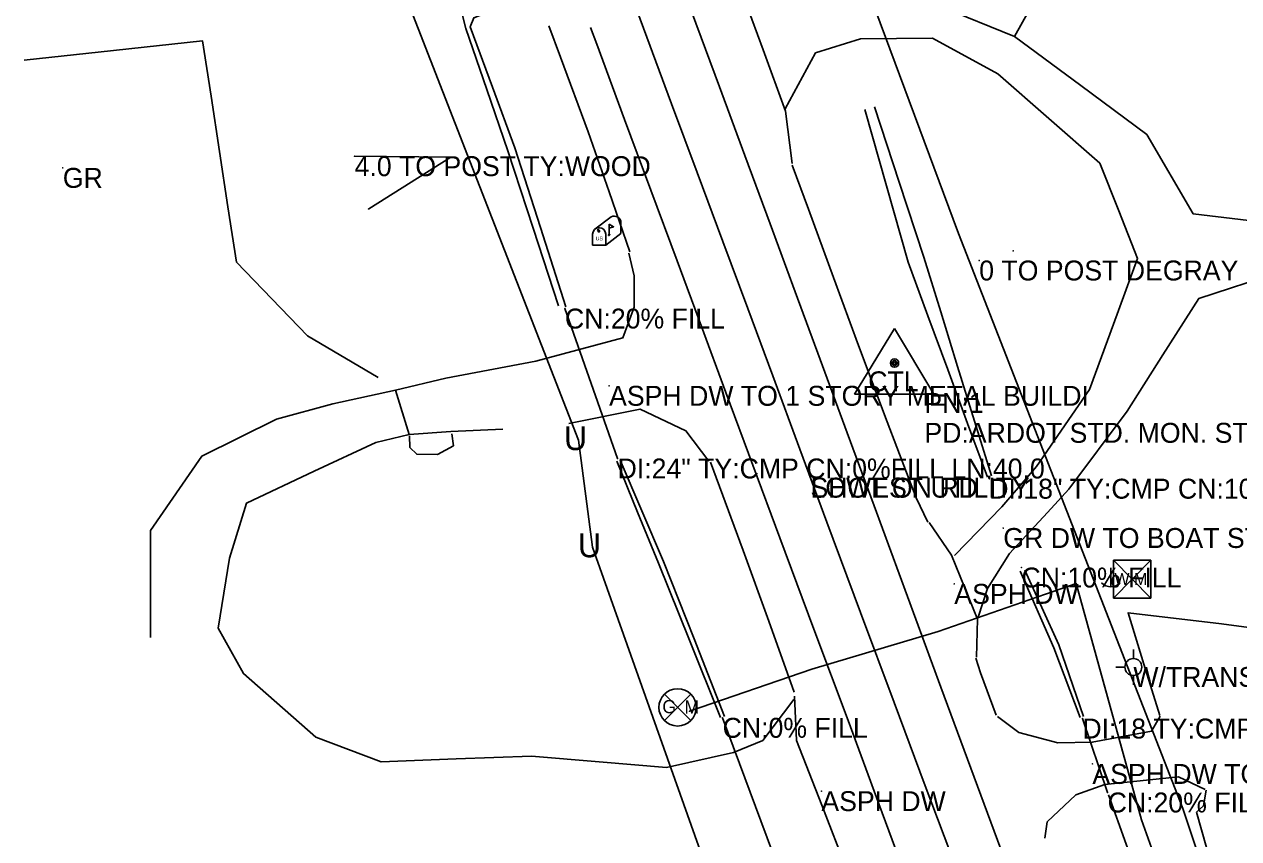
# Model space of a CAD drawing. Extents: x 954793 to 988390, y 1867850 to 1924428.
# Drawn here: x 987769.4 to 988074.1, y 1868561.6 to 1868765.9 of the extents above; entities that cross this region are included whole.
import ezdxf

# ---------------------------------------------------------------- set-up
doc = ezdxf.new("R2010")
doc.units = 0
for name, color, linetype in [('Default', 7, 'Continuous'), ('S_DITCHLINE', 7, 'Continuous'), ('S_DRG_PT_SYM', 7, 'Continuous'), ('S_DRIVEWAY', 7, 'Continuous'), ('S_EDGE_CONCRETE', 7, 'Continuous'), ('S_EDGE_PAVEMENT', 7, 'Continuous'), ('S_ELECTRIC_UTILITIES_ANNOT', 7, 'Continuous'), ('S_FIBER_OPTIC_CABLE', 7, 'Continuous'), ('S_GAS_UTILITIES', 7, 'Continuous'), ('S_GRD_PT_SYM', 7, 'Continuous'), ('S_MAILBOX', 7, 'Continuous'), ('S_MISC_TOPO_POINT', 7, 'Continuous'), ('S_MSC_PT_SYM', 7, 'Continuous'), ('S_PARKING', 7, 'Continuous'), ('S_PAVEMENT_CROWN', 7, 'Continuous'), ('S_PRIMARY_CTL', 7, 'Continuous'), ('S_PRIMARY_CTL_ANNOT', 7, 'Continuous'), ('S_SHOULDER', 7, 'Continuous'), ('S_SIDE_DRAIN', 7, 'Continuous'), ('S_SIDE_DRAIN_ANNOT', 7, 'Continuous'), ('S_SIGN', 7, 'Continuous'), ('S_SIGN_ANNOT', 7, 'Continuous'), ('S_SURVEY_TEXT_ANNOT', 7, 'Continuous'), ('S_TRAILS', 7, 'Continuous'), ('S_UNDERGROUND_CABLE', 7, 'Continuous'), ('S_UTILITY_POLE', 7, 'Continuous'), ('S_UTILITY_POLE_ANNOT', 7, 'Continuous'), ('S_UTL_PT_SYM', 7, 'Continuous'), ('S_WATER_UTILITIES', 7, 'Continuous')]:
    doc.layers.add(name, color=color, linetype=linetype)

msp = doc.modelspace()

# ---------------------------------------------------------------- linework, layer by layer
at = {"layer": 'S_DITCHLINE'}
for points in [[(987903.49, 1868695.28), (987897.13, 1868714.75), (987890.76, 1868734.22), (987885.5, 1868749.56), (987880.23, 1868764.91), (987878.83, 1868770.15), (987872.06, 1868784.34), (987865.3, 1868798.52), (987858.54, 1868812.7), (987851.78, 1868826.88), (987846.31, 1868841.55), (987840.85, 1868856.22), (987834.35, 1868875.57), (987827.85, 1868894.92), (987821.35, 1868914.27), (987814.85, 1868933.62), (987807.68, 1868952.16), (987800.51, 1868970.69), (987793.34, 1868989.23), (987786.17, 1869007.76)], [(987905.32, 1868695.02), (987898.91, 1868714.97), (987892.51, 1868734.92), (987886.89, 1868750.13), (987881.26, 1868765.33), (987882.21, 1868767.55), (987892.86, 1868771.75)], [(987980.33, 1868744.56), (987985.73, 1868725.41), (987991.13, 1868706.25), (987996.11, 1868692.76), (988001.09, 1868679.27), (988006.06, 1868665.78), (988011.04, 1868652.28)], [(987982.74, 1868745.21), (987988.9, 1868726.34), (987995.07, 1868707.48), (987999.32, 1868693.77), (988003.57, 1868680.07), (988007.81, 1868666.36), (988012.06, 1868652.65)], [(987944.08, 1868592.01), (987936.31, 1868611.36), (987928.54, 1868630.7), (987923.3, 1868643.5), (987918.06, 1868656.3)], [(987945.12, 1868592.24), (987937.47, 1868611.69), (987929.83, 1868631.15), (987924.35, 1868643.86), (987918.88, 1868656.56)], [(988034.35, 1868592.01), (988027.69, 1868609.51), (988019.26, 1868628.71)], [(988035.15, 1868592.21), (988028.96, 1868610.19), (988020.44, 1868628.99)], [(988041.44, 1868572.59), (988045.86, 1868560.2), (988050.29, 1868547.82), (988054.72, 1868535.44), (988059.14, 1868523.05)]]:
    msp.add_lwpolyline(points, dxfattribs=at)
at = {"layer": 'S_DRG_PT_SYM'}
for points in [[(987905.07, 1868694.59), (987905.07, 1868694.64), (987905.07, 1868694.59), (987905.02, 1868694.59), (987905.07, 1868694.59), (987905.07, 1868694.54), (987905.07, 1868694.59), (987905.12, 1868694.59)], [(987918.27, 1868656.97), (987918.27, 1868657.02), (987918.27, 1868656.97), (987918.22, 1868656.97), (987918.27, 1868656.97), (987918.27, 1868656.92), (987918.27, 1868656.97), (987918.32, 1868656.97)], [(988011.51, 1868651.9), (988011.51, 1868651.95), (988011.51, 1868651.9), (988011.46, 1868651.9), (988011.51, 1868651.9), (988011.51, 1868651.85), (988011.51, 1868651.9), (988011.56, 1868651.9)], [(988019.58, 1868629.61), (988019.58, 1868629.66), (988019.58, 1868629.61), (988019.53, 1868629.61), (988019.58, 1868629.61), (988019.58, 1868629.56), (988019.58, 1868629.61), (988019.63, 1868629.61)], [(987944.62, 1868591.9), (987944.62, 1868591.95), (987944.62, 1868591.9), (987944.57, 1868591.9), (987944.62, 1868591.9), (987944.62, 1868591.85), (987944.62, 1868591.9), (987944.67, 1868591.9)], [(988034.87, 1868591.72), (988034.87, 1868591.77), (988034.87, 1868591.72), (988034.82, 1868591.72), (988034.87, 1868591.72), (988034.87, 1868591.67), (988034.87, 1868591.72), (988034.92, 1868591.72)], [(988041.2, 1868573.16), (988041.2, 1868573.21), (988041.2, 1868573.16), (988041.15, 1868573.16), (988041.2, 1868573.16), (988041.2, 1868573.11), (988041.2, 1868573.16), (988041.25, 1868573.16)]]:
    msp.add_lwpolyline(points, dxfattribs=at)
at = {"layer": 'S_DRIVEWAY'}
msp.add_line((987857.66, 1868660.97), (987865.96, 1868663.02), dxfattribs=at)
for points in [[(987962.03, 1868730.96), (987960.37, 1868744.14), (987954.75, 1868759.55), (987949.14, 1868774.97), (987943.2, 1868781.9)], [(988084.35, 1868715.79), (988062.66, 1868718.35), (988051.03, 1868738.3), (988034.45, 1868750.58), (988017.86, 1868762.86), (987999.71, 1868770.22), (987977.93, 1868773.05), (987963.85, 1868772.04), (987949.58, 1868775.12)], [(988002.79, 1868632.68), (988014.67, 1868644.85), (988023.39, 1868654.95), (988036.69, 1868674.27), (988042.7, 1868690.71), (988048.71, 1868707.15), (988043.98, 1868719.11), (988039.26, 1868731.06), (988026.45, 1868742.29), (988013.64, 1868753.52), (987997.23, 1868762.45), (987979.17, 1868762.29), (987967.96, 1868758.76), (987960.32, 1868744.73)], [(987889.49, 1868664.37), (987889.47, 1868664.37), (987876.44, 1868663.74), (987865.96, 1868663.02), (987862.6, 1868674.15), (987875.18, 1868677.1), (987897.73, 1868681.36), (987919.55, 1868687.22), (987922.42, 1868694.94), (987922.47, 1868702.78), (987921.13, 1868708.51)], [(988008.75, 1868617.14), (988011.05, 1868624.4), (988016.57, 1868633.1), (988026.12, 1868643.41), (988031.44, 1868649.3), (988046.06, 1868668.83), (988055.06, 1868682.98), (988064.06, 1868697.13), (988084.06, 1868703.69)], [(987862.6, 1868674.15), (987846.84, 1868670.68), (987832.73, 1868666.82), (987813.97, 1868657.55), (987801.11, 1868638.92), (987801.1, 1868625.5), (987801.09, 1868612.08)], [(987941.2, 1868656.29), (987935.42, 1868663.91), (987923.93, 1868669.37), (987906, 1868665.72)], [(987962.48, 1868596.49), (987954.67, 1868586.23), (987947.39, 1868583.22), (987930.55, 1868579.48), (987913.61, 1868580.9), (987896.67, 1868582.32), (987877.82, 1868581.61), (987858.98, 1868580.89), (987842.61, 1868587.03), (987824.39, 1868603.03), (987818.08, 1868614.37), (987820.88, 1868631.96), (987825.2, 1868645.8), (987842.16, 1868653.83), (987857.66, 1868660.97)], [(988008.33, 1868607.12), (988008.53, 1868616.63), (988002.03, 1868632.69), (987996.47, 1868640.88)], [(988054.28, 1868592.51), (988050.3, 1868605.39), (988046.32, 1868618.26), (988069.77, 1868615.5), (988087.92, 1868613.07), (988106.06, 1868610.64), (988126.98, 1868607.84), (988129.98, 1868594.59), (988132.97, 1868581.34)], [(987982.53, 1868545.39), (987975.81, 1868553.73), (987969.49, 1868569.96), (987963.16, 1868586.18), (987962.64, 1868597.36)], [(988013.57, 1868592.27), (988018.93, 1868588.25), (988028.74, 1868585.64), (988037.33, 1868585.79), (988052.24, 1868588.54), (988054.39, 1868592.31)], [(988065.68, 1868573.91), (988058.99, 1868577.08), (988040.51, 1868575.17), (988033.25, 1868572.61), (988026.03, 1868565.78), (988025.41, 1868561.72)], [(988073.78, 1868531.66), (988068.65, 1868549.95), (988063.53, 1868568.24), (988065.28, 1868569.79), (988065.92, 1868573.75)]]:
    msp.add_lwpolyline(points, dxfattribs=at)
at = {"layer": 'S_EDGE_CONCRETE'}
msp.add_lwpolyline([(987876.7, 1868663.18), (987877.12, 1868660.17), (987873.13, 1868658), (987867.91, 1868658.03), (987866.18, 1868659.72), (987866.08, 1868662.65)], dxfattribs=at)
at = {"layer": 'S_EDGE_PAVEMENT'}
for points in [[(988087.92, 1868362.44), (988083.33, 1868374.33), (988078.74, 1868386.23), (988074.15, 1868398.13), (988069.56, 1868410.02), (988061.2, 1868432.59), (988052.85, 1868455.16), (988045.81, 1868474.26), (988038.77, 1868493.37), (988034.38, 1868505.17), (988029.98, 1868516.96), (988022.2, 1868537.95), (988014.42, 1868558.95), (988006.89, 1868579.28), (987999.36, 1868599.62), (987991.01, 1868622.37), (987982.66, 1868645.12), (987975.89, 1868663.45), (987969.13, 1868681.78), (987962.84, 1868698.82), (987956.56, 1868715.86), (987950.21, 1868733.04), (987943.85, 1868750.23), (987936.81, 1868769.13)], [(987991.56, 1868549.36), (987983.82, 1868570.3), (987976.09, 1868591.24), (987967.51, 1868614.15), (987958.93, 1868637.07), (987952.19, 1868655.33), (987945.45, 1868673.58), (987939.33, 1868690.06), (987933.21, 1868706.54), (987926.62, 1868724.29), (987920.03, 1868742.04), (987913.06, 1868760.92), (987911.5, 1868765.16)]]:
    msp.add_lwpolyline(points, dxfattribs=at)
at = {"layer": 'S_FIBER_OPTIC_CABLE'}
for p, q in [((988003.79, 1868713.46), (987979.41, 1868779.14)), ((988060.06, 1868569.17), (988003.79, 1868713.46)), ((988084.77, 1868494.79), (988060.06, 1868569.17))]:
    msp.add_line(p, q, dxfattribs=at)
at = {"layer": 'S_GAS_UTILITIES'}
for p, q in [((988033.28, 1868625.59), (987998.69, 1868613.56)), ((988049.72, 1868566.28), (988033.28, 1868625.59)), ((987998.69, 1868613.56), (987967.02, 1868604.12)), ((987967.02, 1868604.12), (987936.32, 1868593.56)), ((987930.01, 1868591.22), (987936.63, 1868597.84)), ((987930.01, 1868597.84), (987936.63, 1868591.22)), ((988074.37, 1868497.19), (988049.72, 1868566.28))]:
    msp.add_line(p, q, dxfattribs=at)
msp.add_circle((987933.32, 1868594.53), 4.68, dxfattribs=at)
at = {"layer": 'S_GRD_PT_SYM'}
msp.add_lwpolyline([(987966.66, 1868652.16), (987966.66, 1868652.21), (987966.66, 1868652.16), (987966.61, 1868652.16), (987966.66, 1868652.16), (987966.66, 1868652.11), (987966.66, 1868652.16), (987966.71, 1868652.16)], dxfattribs=at)
at = {"layer": 'S_MAILBOX'}
for p, q in [((987912.55, 1868714.5), (987916.69, 1868717.61)), ((987916.17, 1868715.79), (987916.17, 1868713.08)), ((987919.12, 1868716.14), (987919.12, 1868713.42)), ((987912, 1868713.23), (987912, 1868710.51)), ((987915.32, 1868710.51), (987919.12, 1868713.42)), ((987915.32, 1868713.23), (987915.32, 1868710.51)), ((987912, 1868710.51), (987915.32, 1868710.51))]:
    msp.add_line(p, q, dxfattribs=at)
for points in [[(987913.18, 1868714.34), (987913.4, 1868714.21), (987913.4, 1868713.82), (987913.71, 1868713.82), (987913.71, 1868714.18), (987913.52, 1868714.43), (987913.18, 1868714.37)], [(987916.17, 1868715.79), (987917.28, 1868715.13), (987916.17, 1868714.78)]]:
    msp.add_lwpolyline(points, dxfattribs=at)
for centre, end in [((987917.46, 1868716.14), 117.5718), ((987913.66, 1868713.23), 180)]:
    msp.add_arc(centre, 1.66, 0, end, dxfattribs=at)
msp.add_ellipse((987916.17, 1868713.08), major_axis=(0.145, 0.132), ratio=0.564646, dxfattribs=at)
at = {"layer": 'S_MSC_PT_SYM'}
for points in [[(987852.3, 1868732.83), (987852.3, 1868732.88), (987852.3, 1868732.83), (987852.25, 1868732.83), (987852.3, 1868732.83), (987852.3, 1868732.78), (987852.3, 1868732.83), (987852.35, 1868732.83)], [(987876.45, 1868732.59), (987876.45, 1868732.64), (987876.45, 1868732.59), (987876.4, 1868732.59), (987876.45, 1868732.59), (987876.45, 1868732.54), (987876.45, 1868732.59), (987876.5, 1868732.59)], [(987779.1, 1868729.89), (987779.1, 1868729.94), (987779.1, 1868729.89), (987779.05, 1868729.89), (987779.1, 1868729.89), (987779.1, 1868729.84), (987779.1, 1868729.89), (987779.15, 1868729.89)], [(987855.83, 1868719.6), (987855.83, 1868719.65), (987855.83, 1868719.6), (987855.78, 1868719.6), (987855.83, 1868719.6), (987855.83, 1868719.55), (987855.83, 1868719.6), (987855.88, 1868719.6)], [(988017.54, 1868709.08), (988017.54, 1868709.13), (988017.54, 1868709.08), (988017.49, 1868709.08), (988017.54, 1868709.08), (988017.54, 1868709.03), (988017.54, 1868709.08), (988017.59, 1868709.08)], [(988008.98, 1868706.65), (988008.98, 1868706.7), (988008.98, 1868706.65), (988008.93, 1868706.65), (988008.98, 1868706.65), (988008.98, 1868706.6), (988008.98, 1868706.65), (988009.03, 1868706.65)], [(987916.14, 1868675.21), (987916.14, 1868675.26), (987916.14, 1868675.21), (987916.09, 1868675.21), (987916.14, 1868675.21), (987916.14, 1868675.16), (987916.14, 1868675.21), (987916.19, 1868675.21)], [(988015.03, 1868639.53), (988015.03, 1868639.58), (988015.03, 1868639.53), (988014.98, 1868639.53), (988015.03, 1868639.53), (988015.03, 1868639.48), (988015.03, 1868639.53), (988015.08, 1868639.53)], [(988002.74, 1868625.51), (988002.74, 1868625.56), (988002.74, 1868625.51), (988002.69, 1868625.51), (988002.74, 1868625.51), (988002.74, 1868625.46), (988002.74, 1868625.51), (988002.79, 1868625.51)], [(988037.38, 1868580.33), (988037.38, 1868580.38), (988037.38, 1868580.33), (988037.33, 1868580.33), (988037.38, 1868580.33), (988037.38, 1868580.28), (988037.38, 1868580.33), (988037.43, 1868580.33)], [(987969.39, 1868573.5), (987969.39, 1868573.55), (987969.39, 1868573.5), (987969.34, 1868573.5), (987969.39, 1868573.5), (987969.39, 1868573.45), (987969.39, 1868573.5), (987969.44, 1868573.5)]]:
    msp.add_lwpolyline(points, dxfattribs=at)
at = {"layer": 'S_PARKING'}
msp.add_lwpolyline([(987858.18, 1868677.29), (987840.49, 1868687.75), (987831.57, 1868697.01), (987822.64, 1868706.26), (987820.52, 1868720.14), (987818.4, 1868734.02), (987816.28, 1868747.9), (987814.16, 1868761.78), (987791.8, 1868759.33), (987769.44, 1868756.89)], dxfattribs=at)
at = {"layer": 'S_PAVEMENT_CROWN'}
msp.add_lwpolyline([(988003.28, 1868553.98), (987995.45, 1868574.85), (987987.63, 1868595.72), (987979.2, 1868618.35), (987970.78, 1868640.98), (987963.99, 1868659.36), (987957.2, 1868677.75), (987950.94, 1868694.6), (987944.68, 1868711.45), (987938.22, 1868728.71), (987931.77, 1868745.98), (987924.74, 1868765), (987917.72, 1868784.02)], dxfattribs=at)
at = {"layer": 'S_PRIMARY_CTL'}
for p, q in [((987987.74, 1868689.62), (987977.71, 1868673.1)), ((987987.74, 1868689.62), (987997.57, 1868673.1)), ((987977.71, 1868673.1), (987997.57, 1868673.1))]:
    msp.add_line(p, q, dxfattribs=at)
for radius in [1.04, 0.609, 0.344]:
    msp.add_circle((987987.74, 1868680.92), radius, dxfattribs=at)
at = {"layer": 'S_SHOULDER'}
for points in [[(987921.36, 1868708.82), (987916.12, 1868723.89), (987910.89, 1868738.96), (987903.94, 1868757.65), (987900.99, 1868765.57)], [(987996.08, 1868641.04), (987993.13, 1868647.1), (987985.9, 1868666.21), (987978.68, 1868685.32), (987972.41, 1868702.43), (987966.13, 1868719.54), (987962.03, 1868730.6)], [(987962.59, 1868598.37), (987956.18, 1868616.15), (987949.77, 1868633.93), (987941.59, 1868656.04)], [(988013.24, 1868592.55), (988009.29, 1868603.2), (988008.12, 1868606.91)]]:
    msp.add_lwpolyline(points, dxfattribs=at)
at = {"layer": 'S_SIDE_DRAIN'}
for p, q in [((987918.27, 1868656.97), (987905.07, 1868694.59)), ((987961.61, 1868546.26), (987944.62, 1868591.9)), ((988034.87, 1868591.72), (988041.2, 1868573.16))]:
    msp.add_line(p, q, dxfattribs=at)
at = {"layer": 'S_SIGN'}
for p, q in [((987852.3, 1868732.83), (987876.45, 1868732.59)), ((987876.45, 1868732.59), (987855.83, 1868719.6))]:
    msp.add_line(p, q, dxfattribs=at)
at = {"layer": 'S_TRAILS'}
msp.add_lwpolyline([(988017.86, 1868762.86), (988028.18, 1868781.48), (988031.66, 1868787.72)], dxfattribs=at)
at = {"layer": 'S_UNDERGROUND_CABLE'}
for p, q in [((987908.46, 1868661.62), (987864.37, 1868774.97)), ((987911.96, 1868634.74), (987908.46, 1868661.62)), ((987940.72, 1868553.68), (987911.96, 1868634.74))]:
    msp.add_line(p, q, dxfattribs=at)
at = {"layer": 'S_UTILITY_POLE'}
for p, q in [((988041.97, 1868629.52), (988041.97, 1868624.79)), ((988047.65, 1868606.77), (988047.65, 1868609.02)), ((988045.56, 1868604.64), (988043.23, 1868604.64)), ((988047.73, 1868600.22), (988047.73, 1868602.55))]:
    msp.add_line(p, q, dxfattribs=at)
msp.add_circle((988047.65, 1868604.66), 2.13, dxfattribs=at)
msp.add_arc((988042.03, 1868628.22), 3.41, 226.3972, 313.6028, dxfattribs=at)
at = {"layer": 'S_UTL_PT_SYM'}
for points in [[(988003.79, 1868713.46), (988003.79, 1868713.51), (988003.79, 1868713.46), (988003.74, 1868713.46), (988003.79, 1868713.46), (988003.79, 1868713.41), (988003.79, 1868713.46), (988003.84, 1868713.46)], [(987966.67, 1868652.16), (987966.67, 1868652.21), (987966.67, 1868652.16), (987966.62, 1868652.16), (987966.67, 1868652.16), (987966.67, 1868652.11), (987966.67, 1868652.16), (987966.72, 1868652.16)], [(988033.28, 1868625.59), (988033.28, 1868625.64), (988033.28, 1868625.59), (988033.23, 1868625.59), (988033.28, 1868625.59), (988033.28, 1868625.54), (988033.28, 1868625.59), (988033.33, 1868625.59)], [(987998.69, 1868613.56), (987998.69, 1868613.61), (987998.69, 1868613.56), (987998.64, 1868613.56), (987998.69, 1868613.56), (987998.69, 1868613.51), (987998.69, 1868613.56), (987998.74, 1868613.56)], [(987967.02, 1868604.12), (987967.02, 1868604.17), (987967.02, 1868604.12), (987966.97, 1868604.12), (987967.02, 1868604.12), (987967.02, 1868604.07), (987967.02, 1868604.12), (987967.07, 1868604.12)], [(987936.32, 1868593.56), (987936.32, 1868593.61), (987936.32, 1868593.56), (987936.27, 1868593.56), (987936.32, 1868593.56), (987936.32, 1868593.51), (987936.32, 1868593.56), (987936.37, 1868593.56)], [(988060.06, 1868569.17), (988060.06, 1868569.22), (988060.06, 1868569.17), (988060.01, 1868569.17), (988060.06, 1868569.17), (988060.06, 1868569.12), (988060.06, 1868569.17), (988060.11, 1868569.17)], [(988049.72, 1868566.28), (988049.72, 1868566.33), (988049.72, 1868566.28), (988049.67, 1868566.28), (988049.72, 1868566.28), (988049.72, 1868566.23), (988049.72, 1868566.28), (988049.77, 1868566.28)]]:
    msp.add_lwpolyline(points, dxfattribs=at)
at = {"layer": 'S_WATER_UTILITIES'}
for p, q in [((988042.71, 1868631.45), (988052.04, 1868631.45)), ((988042.71, 1868631.45), (988042.71, 1868621.96)), ((988042.71, 1868631.45), (988052.04, 1868621.96)), ((988052.04, 1868631.45), (988042.71, 1868621.96)), ((988052.04, 1868631.45), (988052.04, 1868621.96)), ((988042.71, 1868621.96), (988052.04, 1868621.96))]:
    msp.add_line(p, q, dxfattribs=at)

# ---------------------------------------------------------------- texts
at = {"layer": 'Default'}
for p in [(987904.83, 1868659.08), (987908.33, 1868632.19)]:
    msp.add_text('U', height=6, rotation=360, dxfattribs=at).set_placement(p)
at = {"layer": 'S_ELECTRIC_UTILITIES_ANNOT'}
msp.add_text('LOWEST UTILITY', height=5, dxfattribs=at).set_placement((987966.67, 1868647.16))
at = {"layer": 'S_GAS_UTILITIES'}
for s, p in [('G', (987929.5, 1868593.07)), ('M', (987935.06, 1868592.96))]:
    msp.add_text(s, height=3.3, rotation=360, dxfattribs=at).set_placement(p)
at = {"layer": 'S_MAILBOX'}
msp.add_text('US', height=0.96, rotation=360, dxfattribs=at).set_placement((987912.76, 1868711.71))
at = {"layer": 'S_MISC_TOPO_POINT'}
msp.add_text('SHOT ON RD', height=5, dxfattribs=at).set_placement((987966.66, 1868647.16))
at = {"layer": 'S_PRIMARY_CTL'}
msp.add_text('CTL', height=5, rotation=360, dxfattribs=at).set_placement((987981.16, 1868673.84))
at = {"layer": 'S_PRIMARY_CTL_ANNOT'}
for s, p in [('PN:1', (987995.24, 1868668.42)), ('PD:ARDOT STD. MON. STAMPED PN:1', (987995.24, 1868660.92))]:
    msp.add_text(s, height=5, dxfattribs=at).set_placement(p)
at = {"layer": 'S_SIDE_DRAIN_ANNOT'}
for s, p in [('CN:20% FILL', (987905.07, 1868689.59)), ('DI:24" TY:CMP CN:0%FILL LN:40.0', (987918.27, 1868651.97)), ('DI:18" TY:CMP CN:10%FILL LN:24.', (988011.51, 1868646.9)), ('CN:10% FILL', (988019.58, 1868624.61)), ('CN:0% FILL', (987944.62, 1868586.9)), ('DI:18 TY:CMP CN:0%FILL LN:20.0', (988034.87, 1868586.72)), ('CN:20% FILL', (988041.2, 1868568.16))]:
    msp.add_text(s, height=5, dxfattribs=at).set_placement(p)
at = {"layer": 'S_SIGN_ANNOT'}
for s, p in [('4.0 TO POST TY:WOOD', (987852.3, 1868727.83)), ('0 TO POST DEGRAY BOAT STORAGE', (988008.98, 1868701.65))]:
    msp.add_text(s, height=5, dxfattribs=at).set_placement(p)
at = {"layer": 'S_SURVEY_TEXT_ANNOT'}
for s, p in [('GR', (987779.1, 1868724.89)), ('ASPH DW TO 1 STORY METAL BUILDI', (987916.14, 1868670.21)), ('GR DW TO BOAT STORAGE', (988015.03, 1868634.53)), ('ASPH DW', (988002.74, 1868620.51)), ('ASPH DW TO COUNTRY COLLECTIBLES', (988037.38, 1868575.33)), ('ASPH DW', (987969.39, 1868568.5))]:
    msp.add_text(s, height=5, dxfattribs=at).set_placement(p)
at = {"layer": 'S_UTILITY_POLE_ANNOT'}
msp.add_text('W/TRANS AND LIGHT ARM', height=5, dxfattribs=at).set_placement((988047.65, 1868599.66))
at = {"layer": 'S_WATER_UTILITIES'}
msp.add_text('W M', height=3, rotation=360, dxfattribs=at).set_placement((988042.91, 1868625.22))

doc.saveas('drawing.dxf')
